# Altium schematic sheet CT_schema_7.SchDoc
size 371 x 245 mm
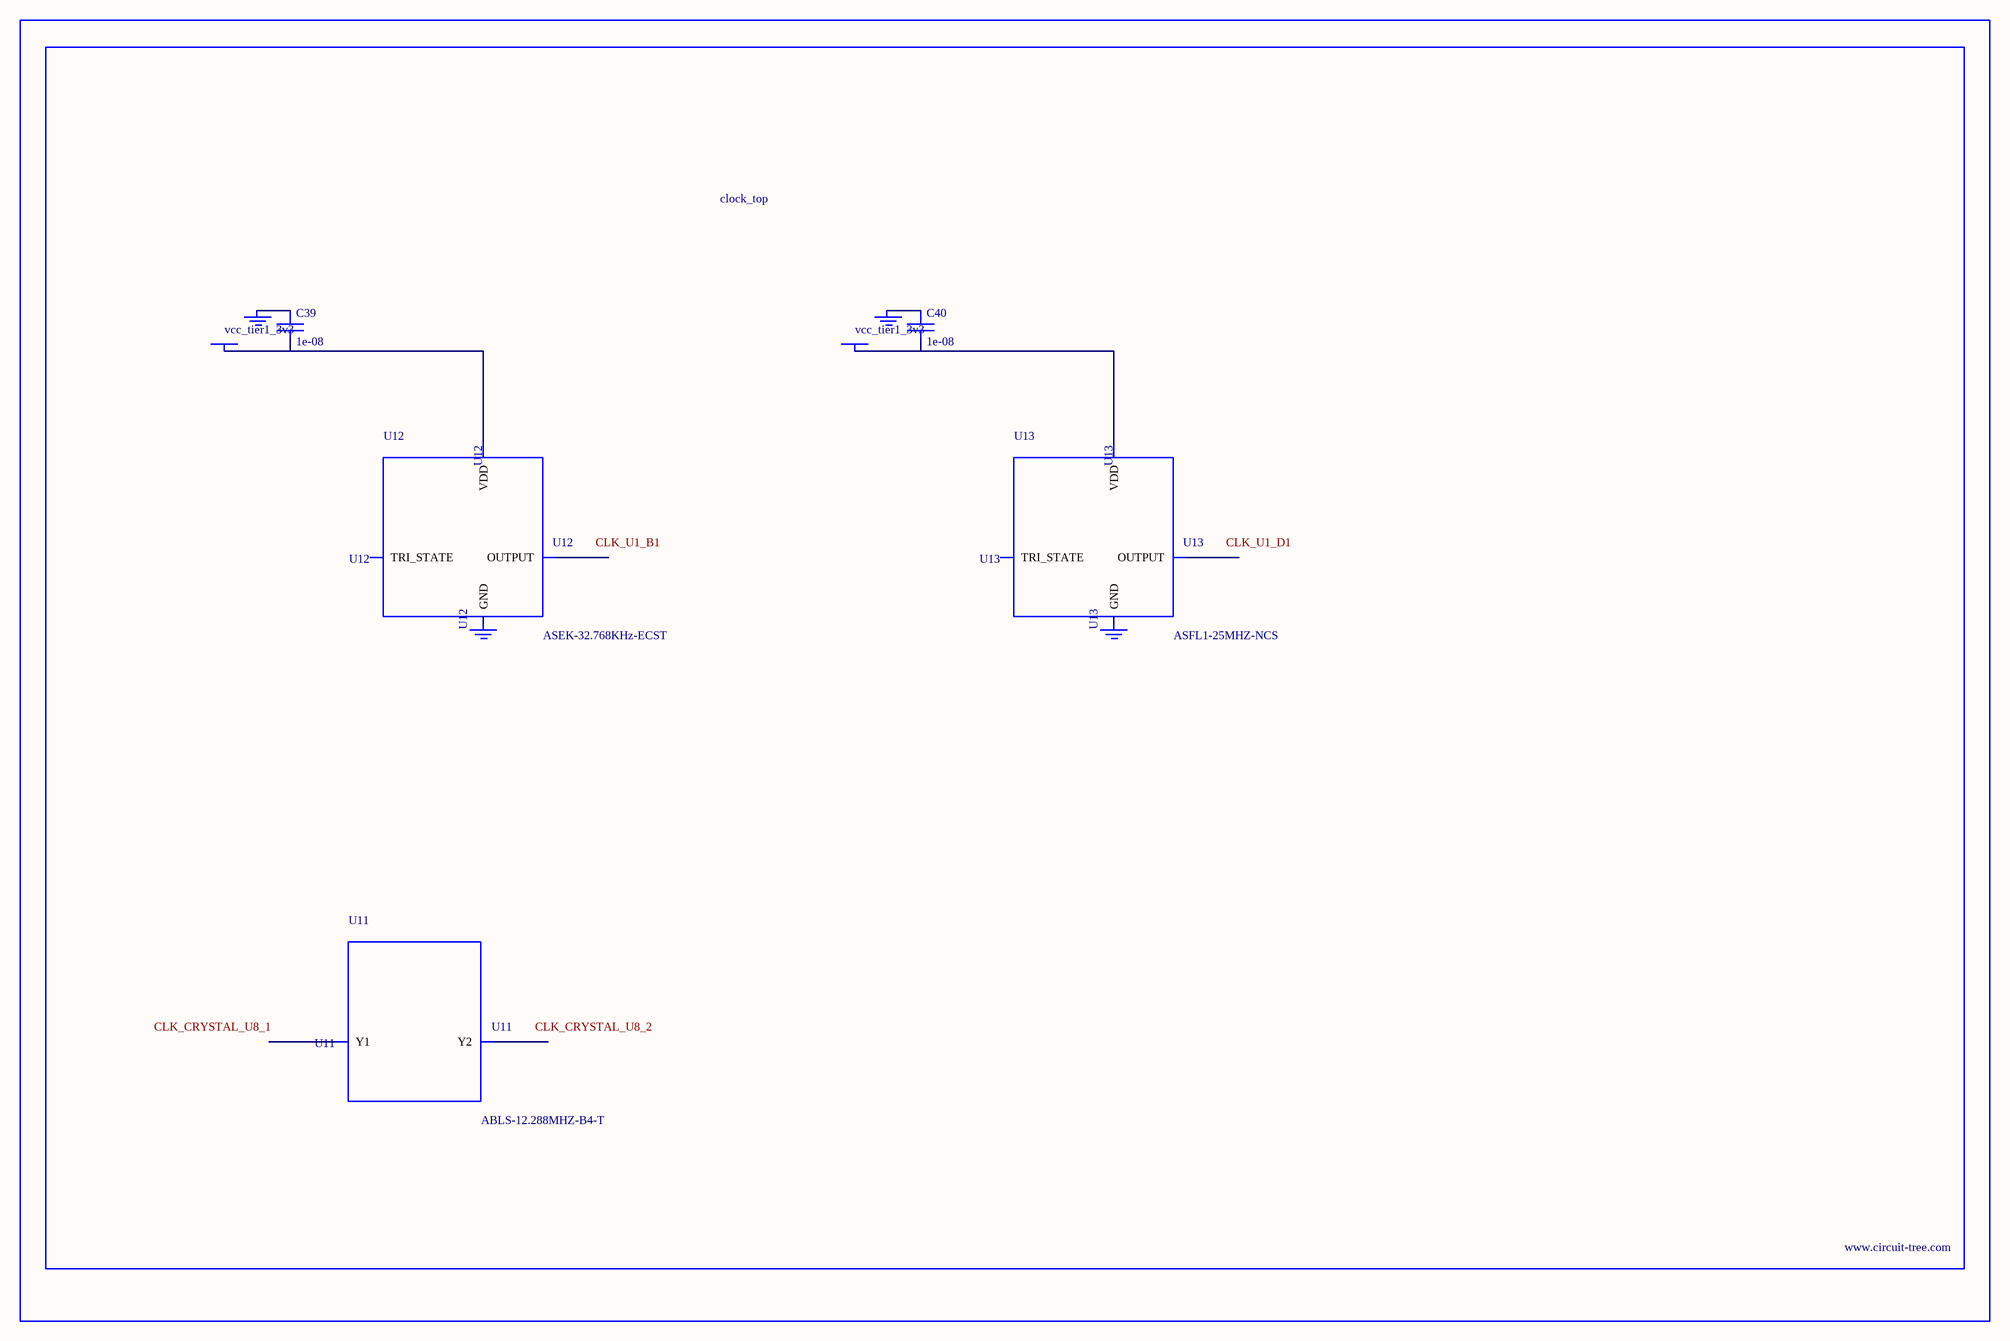
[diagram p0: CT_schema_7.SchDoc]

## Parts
BORDER6  (no value)
C39  1e-08  [C0402]
C40  1e-08  [C0402]
GND_INSTANCE_6_0  (no value)
GND_INSTANCE_6_1  (no value)
GND_INSTANCE_6_2  (no value)
GND_INSTANCE_6_3  (no value)
POWER_INSTANCE_6_0  vcc_tier1_3v3
POWER_INSTANCE_6_1  vcc_tier1_3v3
U11  ABLS-12.288MHZ-B4-T  [ABLS-12.288MHZ-B4-T]
U12  ASEK-32.768KHz-ECST  [ASEK]
U13  ASFL1-25MHZ-NCS  [ASFL1]

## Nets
NetC39_1: C39.1 GND_INSTANCE_6_0.0(GND)
NetC39_2: C39.2 POWER_INSTANCE_6_0.0(PWR) U12.4(VDD)
NetC40_1: C40.1 GND_INSTANCE_6_2.0(GND)
NetC40_2: C40.2 POWER_INSTANCE_6_1.0(PWR) U13.4(VDD)

Not connected (* = marked no-connect by the designer): GND_INSTANCE_6_1 0(GND); GND_INSTANCE_6_3 0(GND); U11 1(Y1) 2(Y2); U12 1(TRI_STATE) 2(GND) 3(OUTPUT); U13 1(TRI_STATE) 2(GND) 3(OUTPUT)

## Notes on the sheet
- Labels drawn without touching a wire or pin: CLK_CRYSTAL_U8_1, CLK_CRYSTAL_U8_2, CLK_U1_B1, CLK_U1_D1

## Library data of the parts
BORDER6 = BORDER_PAGE6
C39 C40 = C0402C103K3RAC
GND_INSTANCE_6_0-GND_INSTANCE_6_3 = GND
POWER_INSTANCE_6_0 POWER_INSTANCE_6_1 = PWR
